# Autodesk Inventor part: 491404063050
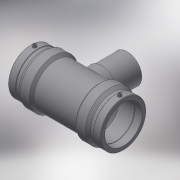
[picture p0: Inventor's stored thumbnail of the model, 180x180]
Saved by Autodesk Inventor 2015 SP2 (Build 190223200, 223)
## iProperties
Created: 2017-06
Part Number: 491404063050
Material: Generic
Description: PLASSON REDUCING TEE 63x50x63
Document SubType Name: Modeling
Designer: KIM
Mass: 382.595 g
Surface Area: 1006.24 cm^2
Volume: 382.595 cm^3
Density: 1 g/cm^3
Appearance: Default
Author: KIM
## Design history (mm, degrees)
derived "491404.ipt"
feature "Solid1::491404.ipt"
tag "TaggingFeature1"
body "Solid1"
other parameters: "d0" = 167, "d1" = 63, "d2" = 82, "d3" = 58, "d4" = 33.4, "d5" = 73.8, "d6" = 59.85, "d7" = 63, "d8" = 168 deg, "d10" = 23.2, "d11" = 7.73333, "d13" = 167, "d14" = 17.6296, "d17" = 56.7, "d18" = 63, "d19" = 3.52592, "d20" = 168 deg, "d22" = 76.26, "d23" = 82, "d25" = 135 deg, "d26" = 116.9, "d29" = 58, "d30" = 15, "d31" = 66.8, "d34" = 5 deg, "d35" = 15, "d39" = 5 deg, "d41" = 4, "d42" = 14, "d43" = 0, "d45" = 4, "d46" = 6, "d47" = 0, "d48" = -109, "d51" = 0, "d54" = 0, "d55" = 73.8, "d56" = 82, "d57" = 58.45, "d58" = 135 deg, "d59" = 58, "d60" = 58, "d61" = 135 deg, "d62" = 109, "d72" = 75.985, "d73" = 37.9925, "d74" = -109, "d75" = 52.5, "d77" = 0, "d80" = 0, "d82" = 68, "d83" = 0, "d84" = 3, "d85" = 0, "d86" = 19.33333, "d87" = 74.7348, "d88" = 7.73333, "d89" = 3, "d90" = 0, "d_" = 63, "L_" = 167, "L_1" = 58, "D_" = 82, "A_" = 58, "d_2" = 12, "H_" = 109
